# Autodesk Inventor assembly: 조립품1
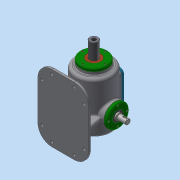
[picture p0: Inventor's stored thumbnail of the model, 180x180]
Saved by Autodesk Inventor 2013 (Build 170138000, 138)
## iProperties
Created: 2019-10
Part Number: 조립품1
Document SubType Name: Assembly
Designer: dgall
Mass: 4941.33 g
Surface Area: 4928.07 cm^2
Volume: 2176.15 cm^3
Density: 2.27067 g/cm^3
Author: dgall
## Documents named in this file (17)
- C:\Users\dgall\Desktop\391004v1015\조립품1.iam
- C:\Users\dgall\Desktop\391004v1015\01본체.ipt
- C:\Users\dgall\Desktop\391004v1015\02개스킷 A.ipt
- C:\Users\dgall\Desktop\391004v1015\03개스킷 B.ipt
- C:\Users\dgall\Desktop\391004v1015\04베어링 6205.ipt
- 베어링 6205.ipt
- C:\Users\dgall\Desktop\391004v1015\05축 커버.ipt
- C:\Users\dgall\Desktop\391004v1015\06오일 실 25 38 8.ipt
- C:\Users\dgall\Desktop\391004v1015\07슬라이드 커버.ipt
- C:\Users\dgall\Desktop\391004v1015\08부시.ipt
- C:\Users\dgall\Desktop\391004v1015\09슬라이드.ipt
- C:\Users\dgall\Desktop\391004v1015\10편심축.ipt
- C:\Users\dgall\Desktop\391004v1015\11볼트 M4x0.7.ipt
- C:\Users\dgall\Desktop\391004v1015\12상부커버.ipt
- C:\Users\dgall\Desktop\391004v1015\13고정플레이트.ipt
- C:\Users\dgall\Desktop\391004v1015\14육각머리볼트 M4.ipt
- C:\Users\dgall\Desktop\391004v1015\15가변스프링.ipt
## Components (29 placed, 14 different names)
1. 01본체:1
2. 02개스킷 A:1
3. 03개스킷 B:1
4. 05축 커버:1 — 각도:1
5. 06오일 실 25 38 8:1
6. 07슬라이드 커버:1
7. 08부시:1
8. 09슬라이드:1
9. 10편심축:1 — 각도:1
10. 12상부커버:1
11. 13고정플레이트:1
12. 14육각머리볼트 M4:1
13. 15가변스프링:1
14. 03개스킷 B:2
15. 05축 커버:2
16. 06오일 실 25 38 8:2
17. 14육각머리볼트 M4:2
18. M4x0.7:3
19. M4x0.7:1
20. M4x0.7:4
21. M4x0.7:5
22. M4x0.7:6
23. M4x0.7:7
24. M4x0.7:8
25. M4x0.7:9
26. M4x0.7:2
27. M4x0.7:10
28. M4x0.7:11
29. M4x0.7:12
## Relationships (1: Angle 1)
- 각도:1 [Angle]: 05축 커버:1 ↔ 10편심축:1
